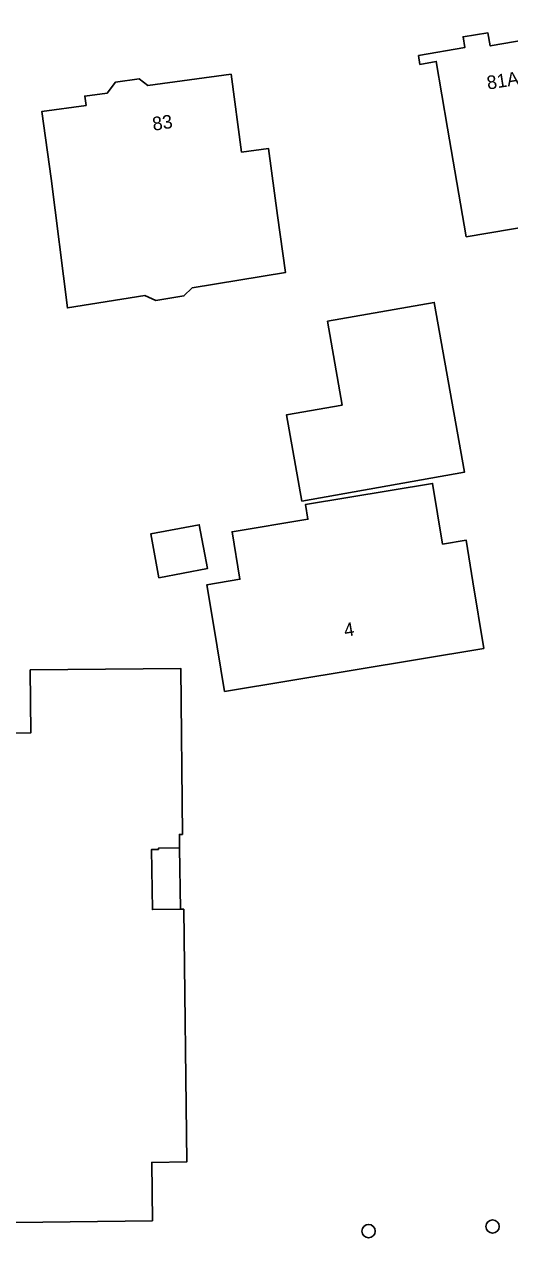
# Model space of a CAD drawing. Extents: x 161772 to 163123, y 383092 to 383917.
# Drawn here: x 162328.5 to 162364.4, y 383533.9 to 383623.5 of the extents above; entities that cross this region are included whole.
import ezdxf

# ---------------------------------------------------------------- set-up
doc = ezdxf.new("R2010")
doc.units = 0
for name, color, linetype in [('IMGEO_Boom', 7, 'Continuous'), ('IMGEO_Pand', 7, 'Continuous'), ('IMGEO_Pand_nummerreeks', 7, 'Continuous'), ('IMGEO_Pand_overbouw', 7, 'Continuous')]:
    doc.layers.add(name, color=color, linetype=linetype)

msp = doc.modelspace()

# ---------------------------------------------------------------- linework, layer by layer
at = {"layer": 'IMGEO_Boom'}
for centre in [(162363.092, 383534.757), (162353.934, 383534.419)]:
    msp.add_circle(centre, 0.489, dxfattribs=at)
at = {"layer": 'IMGEO_Pand'}
for points in [[(162361.135, 383607.772), (162359.769, 383615.794), (162358.93, 383620.723), (162357.724, 383620.505), (162357.632, 383621.161), (162361.053, 383621.754), (162360.917, 383622.55), (162362.74, 383622.839), (162362.922, 383621.868), (162372.254, 383623.468), (162373.093, 383618.539), (162374.539, 383610.05), (162361.135, 383607.772)], [(162347.215, 383609.359), (162347.791, 383605.14), (162340.908, 383604.027), (162340.297, 383603.418), (162338.234, 383603.084), (162337.412, 383603.461), (162331.698, 383602.537), (162330.488, 383612.081), (162329.811, 383617.034), (162333.071, 383617.48), (162332.977, 383618.169), (162334.639, 383618.395), (162335.245, 383619.193), (162336.99, 383619.431), (162337.638, 383618.939), (162343.775, 383619.777), (162344.558, 383614.043), (162346.539, 383614.313), (162347.215, 383609.359)], [(162349.004, 383588.276), (162347.871, 383594.645), (162351.974, 383595.369), (162350.907, 383601.558), (162358.785, 383602.948), (162361.015, 383590.415), (162349.004, 383588.276)], [(162362.451, 383577.397), (162343.303, 383574.235), (162342.488, 383579.169), (162342.002, 383582.111), (162344.432, 383582.513), (162343.852, 383586.023), (162349.455, 383586.949), (162349.276, 383588.036), (162358.657, 383589.586), (162359.395, 383585.116), (162361.128, 383585.402), (162361.636, 383582.331), (162362.451, 383577.397)], [(162338.455, 383582.631), (162337.848, 383585.861), (162341.426, 383586.533), (162342.033, 383583.303), (162338.455, 383582.631)], [(162322.141, 383571.122), (162328.987, 383571.183), (162328.946, 383575.832), (162340.076, 383575.93), (162340.183, 383563.691), (162339.964, 383563.687), (162339.981, 383562.697), (162338.411, 383562.671), (162338.412, 383562.581), (162337.902, 383562.572), (162337.975, 383558.144), (162340.036, 383558.169), (162340.285, 383558.172), (162340.511, 383539.518), (162337.921, 383539.489), (162337.976, 383535.181), (162323.787, 383534.999)]]:
    msp.add_lwpolyline(points, dxfattribs=at)
at = {"layer": 'IMGEO_Pand_overbouw'}
msp.add_lwpolyline([(162339.981, 383562.697), (162338.411, 383562.671), (162338.412, 383562.581), (162337.902, 383562.572), (162337.975, 383558.144), (162340.036, 383558.169)], close=True, dxfattribs=at)

# ---------------------------------------------------------------- texts
at = {"layer": 'IMGEO_Pand_nummerreeks'}
for s, rotation, p in [('81A-81C', 8.8592, (162362.744, 383618.644)), ('83', 8.46832, (162338.044, 383615.608)), ('4', 9.3769, (162352.198, 383578.258))]:
    msp.add_text(s, height=1, rotation=rotation, dxfattribs=at).set_placement(p)

doc.saveas('drawing.dxf')
